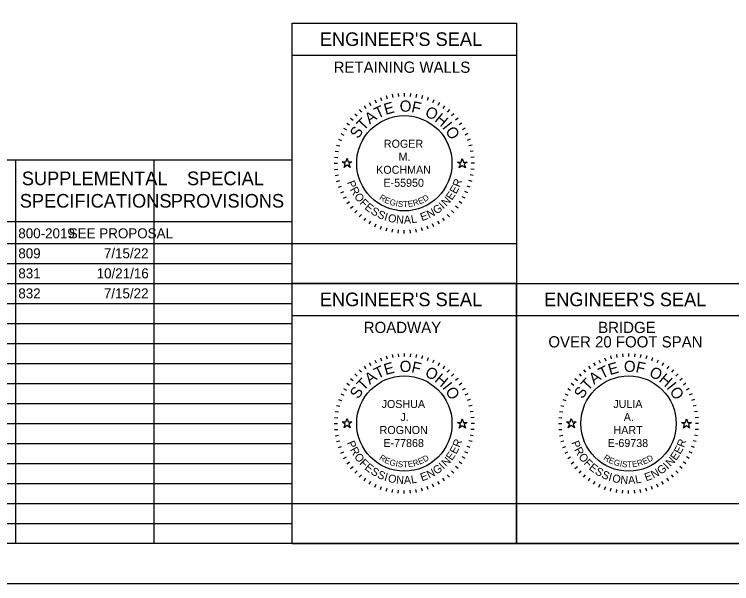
# Model space of a CAD drawing. Extents: x 0 to 34, y 0 to 22.
# Drawn here: x 20.13 to 29.09, y 0 to 7.11 of the extents above; entities that cross this region are included whole.
import ezdxf

# ---------------------------------------------------------------- set-up
doc = ezdxf.new("R2010")
doc.units = 0
for name, color, linetype in [('GM_X_Adjacent_County', 7, 'Continuous'), ('GM_X_County', 7, 'Continuous'), ('GM_X_Section', 7, 'Continuous'), ('GM_X_Township', 7, 'Continuous')]:
    doc.layers.add(name, color=color, linetype=linetype)

msp = doc.modelspace()

# ---------------------------------------------------------------- linework, layer by layer
at = {"layer": 'GM_X_County'}
msp.add_lwpolyline([(1.5, 21.5), (33.5, 21.5), (33.5, 0.5), (1.5, 0.5)], close=True, dxfattribs=at)
at = {"layer": 'GM_X_Section'}
msp.add_lwpolyline([(0, 0), (34, 0), (34, 22), (0, 22)], close=True, dxfattribs=at)
at = {"layer": 'GM_X_Township'}
for p, q in [((23.6, 3.75), (23.6, 7)), ((23.6, 7), (26.4, 7)), ((26.4, 7), (26.4, 3.75)), ((23.6, 6.6), (26.4, 6.6)), ((24.7735, 6.0952), (24.7839, 6.0565)), ((24.8481, 6.1117), (24.855, 6.0723)), ((24.9237, 6.1217), (24.9272, 6.0818)), ((25, 6.125), (25, 6.085)), ((25.0763, 6.1217), (25.0728, 6.0818)), ((25.1519, 6.1117), (25.145, 6.0723)), ((25.2265, 6.0952), (25.2161, 6.0565)), ((24.5625, 6.0078), (24.5825, 5.9731)), ((24.6302, 6.043), (24.6471, 6.0068)), ((24.7007, 6.0722), (24.7144, 6.0346)), ((25.2993, 6.0722), (25.2856, 6.0346)), ((25.3698, 6.043), (25.3529, 6.0068)), ((25.4375, 6.0078), (25.4175, 5.9731)), ((24.4376, 5.9203), (24.4633, 5.8896)), ((24.4981, 5.9668), (24.5211, 5.934)), ((25.5019, 5.9668), (25.4789, 5.934)), ((25.5624, 5.9203), (25.5367, 5.8896)), ((24.3813, 5.8687), (24.4096, 5.8404)), ((25.6187, 5.8687), (25.5904, 5.8404)), ((24.2832, 5.7519), (24.316, 5.7289)), ((24.3297, 5.8124), (24.3604, 5.7867)), ((25.6703, 5.8124), (25.6396, 5.7867)), ((25.7168, 5.7519), (25.684, 5.7289)), ((24.2422, 5.6875), (24.2769, 5.6675)), ((25.7578, 5.6875), (25.7231, 5.6675)), ((24.207, 5.6198), (24.2432, 5.6029)), ((25.793, 5.6198), (25.7568, 5.6029)), ((24.1548, 5.4765), (24.1935, 5.4661)), ((24.1778, 5.5493), (24.2154, 5.5356)), ((25.8222, 5.5493), (25.7846, 5.5356)), ((25.8452, 5.4765), (25.8065, 5.4661)), ((24.1383, 5.4019), (24.1777, 5.395)), ((25.8617, 5.4019), (25.8223, 5.395)), ((10.15, 5.2917), (23.6, 5.2917)), ((20.15, 0.5), (20.15, 5.2917)), ((21.875, 0.5), (21.875, 5.2917)), ((23.6, 0.5), (23.6, 5.2917)), ((24.1283, 5.3263), (24.1682, 5.3228)), ((25.8717, 5.3263), (25.8318, 5.3228)), ((24.125, 5.25), (24.165, 5.25)), ((25.875, 5.25), (25.835, 5.25)), ((24.1283, 5.1737), (24.1682, 5.1772)), ((25.8717, 5.1737), (25.8318, 5.1772)), ((24.1383, 5.0981), (24.1777, 5.105)), ((24.1548, 5.0235), (24.1935, 5.0339)), ((25.8452, 5.0235), (25.8065, 5.0339)), ((25.8617, 5.0981), (25.8223, 5.105)), ((24.1778, 4.9507), (24.2154, 4.9644)), ((25.8222, 4.9507), (25.7846, 4.9644)), ((24.207, 4.8802), (24.2432, 4.8971)), ((25.793, 4.8802), (25.7568, 4.8971)), ((24.2422, 4.8125), (24.2769, 4.8325)), ((24.2832, 4.7481), (24.316, 4.7711)), ((25.7168, 4.7481), (25.684, 4.7711)), ((25.7578, 4.8125), (25.7231, 4.8325)), ((24.3297, 4.6876), (24.3604, 4.7133)), ((24.3813, 4.6313), (24.4096, 4.6596)), ((25.6187, 4.6313), (25.5904, 4.6596)), ((25.6703, 4.6876), (25.6396, 4.7133)), ((24.4376, 4.5797), (24.4633, 4.6104)), ((25.5624, 4.5797), (25.5367, 4.6104)), ((10.15, 4.5209), (23.6, 4.5209)), ((24.4981, 4.5332), (24.5211, 4.566)), ((24.5625, 4.4922), (24.5825, 4.5269)), ((24.6302, 4.457), (24.6471, 4.4932)), ((25.3698, 4.457), (25.3529, 4.4932)), ((25.4375, 4.4922), (25.4175, 4.5269)), ((25.5019, 4.5332), (25.4789, 4.566)), ((24.7007, 4.4278), (24.7144, 4.4654)), ((24.7735, 4.4048), (24.7839, 4.4435)), ((24.8481, 4.3883), (24.855, 4.4277)), ((24.9237, 4.3783), (24.9272, 4.4182)), ((25, 4.375), (25, 4.415)), ((25.0763, 4.3783), (25.0728, 4.4182)), ((25.1519, 4.3883), (25.145, 4.4277)), ((25.2265, 4.4048), (25.2161, 4.4435)), ((25.2993, 4.4278), (25.2856, 4.4654)), ((10.15, 4.25), (23.6, 4.25)), ((10.15, 4), (23.6, 4)), ((10.15, 3.75), (23.6, 3.75)), ((23.6, 0.5), (23.6, 3.75)), ((23.6, 3.75), (26.4, 3.75)), ((23.6, 3.75), (26.4, 3.75)), ((26.4, 3.75), (26.4, 0.5)), ((26.4, 0.5), (26.4, 3.75)), ((26.4, 3.75), (29.2, 3.75)), ((10.15, 3.5), (23.6, 3.5)), ((23.6, 3.35), (26.4, 3.35)), ((26.4, 3.35), (29.2, 3.35)), ((10.15, 3.25), (23.6, 3.25)), ((10.15, 3), (23.6, 3)), ((24.9237, 2.8717), (24.9272, 2.8318)), ((25, 2.875), (25, 2.835)), ((25.0763, 2.8717), (25.0728, 2.8318)), ((27.7237, 2.8717), (27.7272, 2.8318)), ((27.8, 2.875), (27.8, 2.835)), ((27.8763, 2.8717), (27.8728, 2.8318)), ((24.6302, 2.793), (24.6471, 2.7568)), ((24.7007, 2.8222), (24.7144, 2.7846)), ((24.7735, 2.8452), (24.7839, 2.8065)), ((24.8481, 2.8617), (24.855, 2.8223)), ((25.1519, 2.8617), (25.145, 2.8223)), ((25.2265, 2.8452), (25.2161, 2.8065)), ((25.2993, 2.8222), (25.2856, 2.7846)), ((25.3698, 2.793), (25.3529, 2.7568)), ((27.4302, 2.793), (27.4471, 2.7568)), ((27.5007, 2.8222), (27.5144, 2.7846)), ((27.5735, 2.8452), (27.5839, 2.8065)), ((27.6481, 2.8617), (27.655, 2.8223)), ((27.9519, 2.8617), (27.945, 2.8223)), ((28.0265, 2.8452), (28.0161, 2.8065)), ((28.0993, 2.8222), (28.0856, 2.7846)), ((28.1698, 2.793), (28.1529, 2.7568)), ((10.15, 2.75), (23.6, 2.75)), ((24.4981, 2.7168), (24.5211, 2.684)), ((24.5625, 2.7578), (24.5825, 2.7231)), ((25.4375, 2.7578), (25.4175, 2.7231)), ((25.5019, 2.7168), (25.4789, 2.684)), ((27.2981, 2.7168), (27.3211, 2.684)), ((27.3625, 2.7578), (27.3825, 2.7231)), ((28.2375, 2.7578), (28.2175, 2.7231)), ((28.3019, 2.7168), (28.2789, 2.684)), ((24.3813, 2.6187), (24.4096, 2.5904)), ((24.4376, 2.6703), (24.4633, 2.6396)), ((25.5624, 2.6703), (25.5367, 2.6396)), ((25.6187, 2.6187), (25.5904, 2.5904)), ((27.1813, 2.6187), (27.2096, 2.5904)), ((27.2376, 2.6703), (27.2633, 2.6396)), ((28.3624, 2.6703), (28.3367, 2.6396)), ((28.4187, 2.6187), (28.3904, 2.5904)), ((24.3297, 2.5624), (24.3604, 2.5367)), ((25.6703, 2.5624), (25.6396, 2.5367)), ((27.1297, 2.5624), (27.1604, 2.5367)), ((28.4703, 2.5624), (28.4396, 2.5367)), ((10.15, 2.5), (23.6, 2.5)), ((24.2422, 2.4375), (24.2769, 2.4175)), ((24.2832, 2.5019), (24.316, 2.4789)), ((25.7168, 2.5019), (25.684, 2.4789)), ((25.7578, 2.4375), (25.7231, 2.4175)), ((27.0422, 2.4375), (27.0769, 2.4175)), ((27.0832, 2.5019), (27.116, 2.4789)), ((28.5168, 2.5019), (28.484, 2.4789)), ((28.5578, 2.4375), (28.5231, 2.4175)), ((24.207, 2.3698), (24.2432, 2.3529)), ((25.793, 2.3698), (25.7568, 2.3529)), ((27.007, 2.3698), (27.0432, 2.3529)), ((28.593, 2.3698), (28.5568, 2.3529)), ((10.15, 2.25), (23.6, 2.25)), ((24.1778, 2.2993), (24.2154, 2.2856)), ((25.8222, 2.2993), (25.7846, 2.2856)), ((26.9778, 2.2993), (27.0154, 2.2856)), ((28.6222, 2.2993), (28.5846, 2.2856)), ((24.1383, 2.1519), (24.1777, 2.145)), ((24.1548, 2.2265), (24.1935, 2.2161)), ((25.8452, 2.2265), (25.8065, 2.2161)), ((25.8617, 2.1519), (25.8223, 2.145)), ((26.9383, 2.1519), (26.9777, 2.145)), ((26.9548, 2.2265), (26.9935, 2.2161)), ((28.6452, 2.2265), (28.6065, 2.2161)), ((28.6617, 2.1519), (28.6223, 2.145)), ((24.1283, 2.0763), (24.1682, 2.0728)), ((25.8717, 2.0763), (25.8318, 2.0728)), ((26.9283, 2.0763), (26.9682, 2.0728)), ((28.6717, 2.0763), (28.6318, 2.0728)), ((10.15, 2), (23.6, 2)), ((24.125, 2), (24.165, 2)), ((25.875, 2), (25.835, 2)), ((26.925, 2), (26.965, 2)), ((28.675, 2), (28.635, 2)), ((24.1283, 1.9237), (24.1682, 1.9272)), ((25.8717, 1.9237), (25.8318, 1.9272)), ((26.9283, 1.9237), (26.9682, 1.9272)), ((28.6717, 1.9237), (28.6318, 1.9272)), ((24.1383, 1.8481), (24.1777, 1.855)), ((25.8617, 1.8481), (25.8223, 1.855)), ((26.9383, 1.8481), (26.9777, 1.855)), ((28.6617, 1.8481), (28.6223, 1.855)), ((10.15, 1.75), (23.6, 1.75)), ((24.1548, 1.7735), (24.1935, 1.7839)), ((24.1778, 1.7007), (24.2154, 1.7144)), ((25.8222, 1.7007), (25.7846, 1.7144)), ((25.8452, 1.7735), (25.8065, 1.7839)), ((26.9548, 1.7735), (26.9935, 1.7839)), ((26.9778, 1.7007), (27.0154, 1.7144)), ((28.6222, 1.7007), (28.5846, 1.7144)), ((28.6452, 1.7735), (28.6065, 1.7839)), ((24.207, 1.6302), (24.2432, 1.6471)), ((25.793, 1.6302), (25.7568, 1.6471)), ((27.007, 1.6302), (27.0432, 1.6471)), ((28.593, 1.6302), (28.5568, 1.6471)), ((24.2422, 1.5625), (24.2769, 1.5825)), ((25.7578, 1.5625), (25.7231, 1.5825)), ((27.0422, 1.5625), (27.0769, 1.5825)), ((28.5578, 1.5625), (28.5231, 1.5825)), ((10.15, 1.5), (23.6, 1.5)), ((24.2832, 1.4981), (24.316, 1.5211)), ((24.3297, 1.4376), (24.3604, 1.4633)), ((25.6703, 1.4376), (25.6396, 1.4633)), ((25.7168, 1.4981), (25.684, 1.5211)), ((27.0832, 1.4981), (27.116, 1.5211)), ((27.1297, 1.4376), (27.1604, 1.4633)), ((28.4703, 1.4376), (28.4396, 1.4633)), ((28.5168, 1.4981), (28.484, 1.5211)), ((24.3813, 1.3813), (24.4096, 1.4096)), ((24.4376, 1.3297), (24.4633, 1.3604)), ((25.5624, 1.3297), (25.5367, 1.3604)), ((25.6187, 1.3813), (25.5904, 1.4096)), ((27.1813, 1.3813), (27.2096, 1.4096)), ((27.2376, 1.3297), (27.2633, 1.3604)), ((28.3624, 1.3297), (28.3367, 1.3604)), ((28.4187, 1.3813), (28.3904, 1.4096)), ((24.4981, 1.2832), (24.5211, 1.316)), ((24.5625, 1.2422), (24.5825, 1.2769)), ((25.4375, 1.2422), (25.4175, 1.2769)), ((25.5019, 1.2832), (25.4789, 1.316)), ((27.2981, 1.2832), (27.3211, 1.316)), ((27.3625, 1.2422), (27.3825, 1.2769)), ((28.2375, 1.2422), (28.2175, 1.2769)), ((28.3019, 1.2832), (28.2789, 1.316)), ((10.15, 1.25), (23.6, 1.25)), ((24.6302, 1.207), (24.6471, 1.2432)), ((24.7007, 1.1778), (24.7144, 1.2154)), ((24.7735, 1.1548), (24.7839, 1.1935)), ((24.8481, 1.1383), (24.855, 1.1777)), ((24.9237, 1.1283), (24.9272, 1.1682)), ((25, 1.125), (25, 1.165)), ((25.0763, 1.1283), (25.0728, 1.1682)), ((25.1519, 1.1383), (25.145, 1.1777)), ((25.2265, 1.1548), (25.2161, 1.1935)), ((25.2993, 1.1778), (25.2856, 1.2154)), ((25.3698, 1.207), (25.3529, 1.2432)), ((27.4302, 1.207), (27.4471, 1.2432)), ((27.5007, 1.1778), (27.5144, 1.2154)), ((27.5735, 1.1548), (27.5839, 1.1935)), ((27.6481, 1.1383), (27.655, 1.1777)), ((27.7237, 1.1283), (27.7272, 1.1682)), ((27.8, 1.125), (27.8, 1.165)), ((27.8763, 1.1283), (27.8728, 1.1682)), ((27.9519, 1.1383), (27.945, 1.1777)), ((28.0265, 1.1548), (28.0161, 1.1935)), ((28.0993, 1.1778), (28.0856, 1.2154)), ((28.1698, 1.207), (28.1529, 1.2432)), ((10.15, 1), (23.6, 1)), ((10.15, 0.75), (23.6, 0.75)), ((23.6, 0.5), (26.4, 0.5)), ((26.4, 0.5), (29.2, 0.5))]:
    msp.add_line(p, q, dxfattribs=at)
for points in [[(24.2236, 5.27), (24.2705, 5.27), (24.285, 5.3145), (24.2995, 5.27), (24.3464, 5.27), (24.3085, 5.2424), (24.323, 5.1978), (24.285, 5.2254), (24.247, 5.1978), (24.2615, 5.2424)], [(25.6627, 5.2646), (25.7096, 5.2646), (25.7241, 5.3091), (25.7386, 5.2646), (25.7855, 5.2646), (25.7476, 5.237), (25.7621, 5.1924), (25.7241, 5.22), (25.6861, 5.1924), (25.7006, 5.237)], [(23.6, 3.75), (23.6, 4.25), (26.4, 4.25), (26.4, 3.75)], [(24.2236, 2.02), (24.2705, 2.02), (24.285, 2.0645), (24.2995, 2.02), (24.3464, 2.02), (24.3085, 1.9924), (24.323, 1.9478), (24.285, 1.9754), (24.247, 1.9478), (24.2615, 1.9924)], [(27.0236, 2.02), (27.0705, 2.02), (27.085, 2.0645), (27.0995, 2.02), (27.1464, 2.02), (27.1085, 1.9924), (27.123, 1.9478), (27.085, 1.9754), (27.047, 1.9478), (27.0615, 1.9924)], [(25.6627, 2.0146), (25.7096, 2.0146), (25.7241, 2.0591), (25.7386, 2.0146), (25.7855, 2.0146), (25.7476, 1.987), (25.7621, 1.9424), (25.7241, 1.97), (25.6861, 1.9424), (25.7006, 1.987)], [(28.4627, 2.0146), (28.5096, 2.0146), (28.5241, 2.0591), (28.5386, 2.0146), (28.5855, 2.0146), (28.5476, 1.987), (28.5621, 1.9424), (28.5241, 1.97), (28.4861, 1.9424), (28.5006, 1.987)], [(23.6, 0.5), (23.6, 1), (26.4, 1), (26.4, 0.5)], [(26.4, 0.5), (26.4, 1), (29.2, 1), (29.2, 0.5)]]:
    msp.add_lwpolyline(points, close=True, dxfattribs=at)
for centre in [(25, 5.25), (25, 2), (27.8, 2)]:
    msp.add_circle(centre, 0.595, dxfattribs=at)

# ---------------------------------------------------------------- texts
at = {"layer": 'GM_X_Adjacent_County'}
for s, p in [('SUPPLEMENTAL', (20.2237, 4.9763)), ('SPECIAL', (22.2864, 4.9763)), ('SPECIFICATIONS', (20.1982, 4.6963)), ('PROVISIONS', (22.0843, 4.6963))]:
    msp.add_text(s, height=0.17, dxfattribs=at).set_placement(p)
at = {"layer": 'GM_X_Township'}
for s, height, p in [("ENGINEER'S SEAL", 0.17, (23.9448, 6.715)), ('RETAINING WALLS', 0.14, (24.1173, 6.38)), ('ROGER', 0.1, (24.7447, 5.4437)), ('M.', 0.1, (24.9285, 5.2812)), ('KOCHMAN', 0.1, (24.6486, 5.1187)), ('E-55950', 0.1, (24.7393, 4.9562)), ('800-2019', 0.125, (20.18, 4.3125)), ('SEE PROPOSAL', 0.125, (20.8104, 4.3125)), ('809', 0.125, (20.18, 4.0625)), ('7/15/22', 0.125, (21.2482, 4.0625)), ('10/21/16', 0.125, (21.158, 3.8125)), ('831', 0.125, (20.18, 3.8125)), ('832', 0.125, (20.18, 3.5625)), ('7/15/22', 0.125, (21.2482, 3.5625)), ("ENGINEER'S SEAL", 0.17, (23.9448, 3.465)), ("ENGINEER'S SEAL", 0.17, (26.7448, 3.465)), ('ROADWAY', 0.14, (24.4932, 3.13)), ('BRIDGE', 0.14, (27.4205, 3.13)), ('OVER 20 FOOT SPAN', 0.14, (26.7987, 2.95)), ('JOSHUA', 0.1, (24.7165, 2.1938)), ('JULIA', 0.1, (27.6096, 2.1938)), ('J.', 0.1, (24.9518, 2.0312)), ('A.', 0.1, (27.7401, 2.0312)), ('ROGNON', 0.1, (24.6913, 1.8687)), ('HART', 0.1, (27.6125, 1.8687)), ('E-77868', 0.1, (24.7391, 1.7063)), ('E-69738', 0.1, (27.5391, 1.7063))]:
    msp.add_text(s, height=height, dxfattribs=at).set_placement(p)
for s, height, rotation, p in [('E', 0.14, 15.75706, (24.7669, 5.8534)), ('O', 0.14, 359.78119, (24.942, 5.8942)), ('F', 0.14, 347.43619, (25.0811, 5.8917)), ('T', 0.14, 25.71674, (24.6661, 5.804)), ('O', 0.14, 332.25863, (25.2463, 5.8481)), ('T', 0.14, 46.4344, (24.4917, 5.65)), ('A', 0.14, 36.47472, (24.5685, 5.7319)), ('H', 0.14, 319.91363, (25.3684, 5.7816)), ('I', 0.14, 308.36695, (25.4674, 5.6971)), ('S', 0.14, 57.19238, (24.426, 5.5481)), ('O', 0.14, 303.14906, (25.5061, 5.6528)), ('P', 0.1, 291.49398, (24.2823, 5.0119)), ('R', 0.1, 69.23216, (25.6913, 4.9436)), ('R', 0.1, 298.73106, (24.3181, 4.9233)), ('E', 0.1, 61.99508, (25.6472, 4.859)), ('O', 0.1, 306.46664, (24.3682, 4.8345)), ('R', 0.075, 327.82385, (24.6801, 4.804)), ('D', 0.075, 31.46601, (25.255, 4.7636)), ('E', 0.1, 54.75801, (25.5928, 4.7806)), ('F', 0.1, 314.7068, (24.4343, 4.7483)), ('E', 0.1, 321.43929, (24.497, 4.6854)), ('E', 0.075, 337.77772, (24.7439, 4.7628)), ('G', 0.075, 344.27273, (24.8082, 4.7348)), ('I', 0.075, 350.64643, (24.8868, 4.7134)), ('S', 0.075, 353.78581, (24.9155, 4.7081)), ('T', 0.075, 3.00609, (24.9852, 4.7005)), ('E', 0.075, 8.98261, (25.0492, 4.703)), ('R', 0.075, 17.68363, (25.1187, 4.7127)), ('E', 0.075, 23.30524, (25.1909, 4.7356)), ('I', 0.1, 43.28703, (25.4876, 4.6721)), ('N', 0.1, 47.02243, (25.5242, 4.705)), ('S', 0.1, 328.67637, (24.5722, 4.6266)), ('S', 0.1, 335.91345, (24.6541, 4.5776)), ('N', 0.1, 27.31129, (25.3097, 4.5602)), ('G', 0.1, 35.04687, (25.3997, 4.6081)), ('I', 0.1, 343.15053, (24.7416, 4.5394)), ('O', 0.1, 346.88592, (24.7884, 4.5241)), ('N', 0.1, 355.12608, (24.8946, 4.5012)), ('A', 0.1, 2.86166, (24.9964, 4.4939)), ('L', 0.1, 10.09874, (25.0917, 4.4994)), ('E', 0.1, 20.07421, (25.2203, 4.5267)), ('O', 0.14, 359.78119, (24.942, 2.6442)), ('O', 0.14, 359.78119, (27.742, 2.6442)), ('T', 0.14, 25.71674, (24.6661, 2.554)), ('E', 0.14, 15.75706, (24.7669, 2.6034)), ('F', 0.14, 347.43619, (25.0811, 2.6417)), ('O', 0.14, 332.25863, (25.2463, 2.5981)), ('T', 0.14, 25.71674, (27.4661, 2.554)), ('E', 0.14, 15.75706, (27.5669, 2.6034)), ('F', 0.14, 347.43619, (27.8811, 2.6417)), ('O', 0.14, 332.25863, (28.0463, 2.5981)), ('A', 0.14, 36.47472, (24.5685, 2.4819)), ('H', 0.14, 319.91363, (25.3684, 2.5316)), ('A', 0.14, 36.47472, (27.3685, 2.4819)), ('H', 0.14, 319.91363, (28.1684, 2.5316)), ('T', 0.14, 46.4344, (24.4917, 2.4)), ('I', 0.14, 308.36695, (25.4674, 2.4471)), ('T', 0.14, 46.4344, (27.2917, 2.4)), ('I', 0.14, 308.36695, (28.2674, 2.4471)), ('S', 0.14, 57.19238, (24.426, 2.2981)), ('O', 0.14, 303.14906, (25.5061, 2.4028)), ('S', 0.14, 57.19238, (27.226, 2.2981)), ('O', 0.14, 303.14906, (28.3061, 2.4028)), ('R', 0.1, 69.23216, (25.6913, 1.6936)), ('R', 0.1, 69.23216, (28.4913, 1.6936)), ('P', 0.1, 291.49398, (24.2823, 1.7619)), ('R', 0.1, 298.73106, (24.3181, 1.6733)), ('E', 0.1, 61.99508, (25.6472, 1.609)), ('P', 0.1, 291.49398, (27.0823, 1.7619)), ('R', 0.1, 298.73106, (27.1181, 1.6733)), ('E', 0.1, 61.99508, (28.4472, 1.609)), ('O', 0.1, 306.46664, (24.3682, 1.5845)), ('R', 0.075, 327.82385, (24.6801, 1.554)), ('E', 0.1, 54.75801, (25.5928, 1.5306)), ('O', 0.1, 306.46664, (27.1682, 1.5845)), ('R', 0.075, 327.82385, (27.4801, 1.554)), ('E', 0.1, 54.75801, (28.3928, 1.5306)), ('F', 0.1, 314.7068, (24.4343, 1.4983)), ('E', 0.075, 337.77772, (24.7439, 1.5128)), ('G', 0.075, 344.27273, (24.8082, 1.4848)), ('I', 0.075, 350.64643, (24.8868, 1.4634)), ('S', 0.075, 353.78581, (24.9155, 1.4581)), ('T', 0.075, 3.00609, (24.9852, 1.4505)), ('E', 0.075, 8.98261, (25.0492, 1.453)), ('R', 0.075, 17.68363, (25.1187, 1.4627)), ('E', 0.075, 23.30524, (25.1909, 1.4856)), ('D', 0.075, 31.46601, (25.255, 1.5136)), ('N', 0.1, 47.02243, (25.5242, 1.455)), ('F', 0.1, 314.7068, (27.2343, 1.4983)), ('E', 0.075, 337.77772, (27.5439, 1.5128)), ('G', 0.075, 344.27273, (27.6082, 1.4848)), ('I', 0.075, 350.64643, (27.6868, 1.4634)), ('S', 0.075, 353.78581, (27.7155, 1.4581)), ('T', 0.075, 3.00609, (27.7852, 1.4505)), ('E', 0.075, 8.98261, (27.8492, 1.453)), ('R', 0.075, 17.68363, (27.9187, 1.4627)), ('E', 0.075, 23.30524, (27.9909, 1.4856)), ('D', 0.075, 31.46601, (28.055, 1.5136)), ('N', 0.1, 47.02243, (28.3242, 1.455)), ('E', 0.1, 321.43929, (24.497, 1.4354)), ('S', 0.1, 328.67637, (24.5722, 1.3766)), ('N', 0.1, 27.31129, (25.3097, 1.3102)), ('G', 0.1, 35.04687, (25.3997, 1.3581)), ('I', 0.1, 43.28703, (25.4876, 1.4221)), ('E', 0.1, 321.43929, (27.297, 1.4354)), ('S', 0.1, 328.67637, (27.3722, 1.3766)), ('N', 0.1, 27.31129, (28.1097, 1.3102)), ('G', 0.1, 35.04687, (28.1997, 1.3581)), ('I', 0.1, 43.28703, (28.2876, 1.4221)), ('S', 0.1, 335.91345, (24.6541, 1.3276)), ('I', 0.1, 343.15053, (24.7416, 1.2894)), ('O', 0.1, 346.88592, (24.7884, 1.2741)), ('N', 0.1, 355.12608, (24.8946, 1.2512)), ('A', 0.1, 2.86166, (24.9964, 1.2439)), ('L', 0.1, 10.09874, (25.0917, 1.2494)), ('E', 0.1, 20.07421, (25.2203, 1.2767)), ('S', 0.1, 335.91345, (27.4541, 1.3276)), ('I', 0.1, 343.15053, (27.5416, 1.2894)), ('O', 0.1, 346.88592, (27.5884, 1.2741)), ('N', 0.1, 355.12608, (27.6946, 1.2512)), ('A', 0.1, 2.86166, (27.7964, 1.2439)), ('L', 0.1, 10.09874, (27.8917, 1.2494)), ('E', 0.1, 20.07421, (28.0203, 1.2767))]:
    msp.add_text(s, height=height, rotation=rotation, dxfattribs=at).set_placement(p)

doc.saveas('drawing.dxf')
